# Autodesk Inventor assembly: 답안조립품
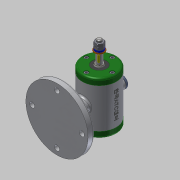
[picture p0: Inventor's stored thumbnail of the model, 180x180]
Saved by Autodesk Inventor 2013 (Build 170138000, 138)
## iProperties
Created: 2018-12
Part Number: 답안조립품
Document SubType Name: Assembly
Designer: Gpr
Author: Gpr
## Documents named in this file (15)
- C:\Users\Administrator\Desktop\481207V1071\답안조립품.iam
- C:\Users\Administrator\Desktop\481207V1071\본체.ipt
- C:\Users\Administrator\Desktop\481207V1071\V벨트풀리.ipt
- C:\Users\Administrator\Desktop\481207V1071\고무캡.ipt
- C:\Users\Administrator\Desktop\481207V1071\너트 M8.ipt
- 너트 M8.ipt
- C:\Users\Administrator\Desktop\481207V1071\뒤커버.ipt
- C:\Users\Administrator\Desktop\481207V1071\베어링 15 x 32 x 9.ipt
- C:\Users\Administrator\Desktop\481207V1071\볼트 M4 x 12.ipt
- C:\Users\Administrator\Desktop\481207V1071\스프링와셔 8.ipt
- C:\Users\Administrator\Desktop\481207V1071\앞커버.ipt
- C:\Users\Administrator\Desktop\481207V1071\오일 실 15 25 7.ipt
- C:\Users\Administrator\Desktop\481207V1071\와셔 8x17.ipt
- C:\Users\Administrator\Desktop\481207V1071\축.ipt
- C:\Users\Administrator\Desktop\481207V1071\키 3 x 3 x 12.ipt
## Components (2 placed, 2 different names)
1. V벨트풀리:1
2. 고무캡:1
